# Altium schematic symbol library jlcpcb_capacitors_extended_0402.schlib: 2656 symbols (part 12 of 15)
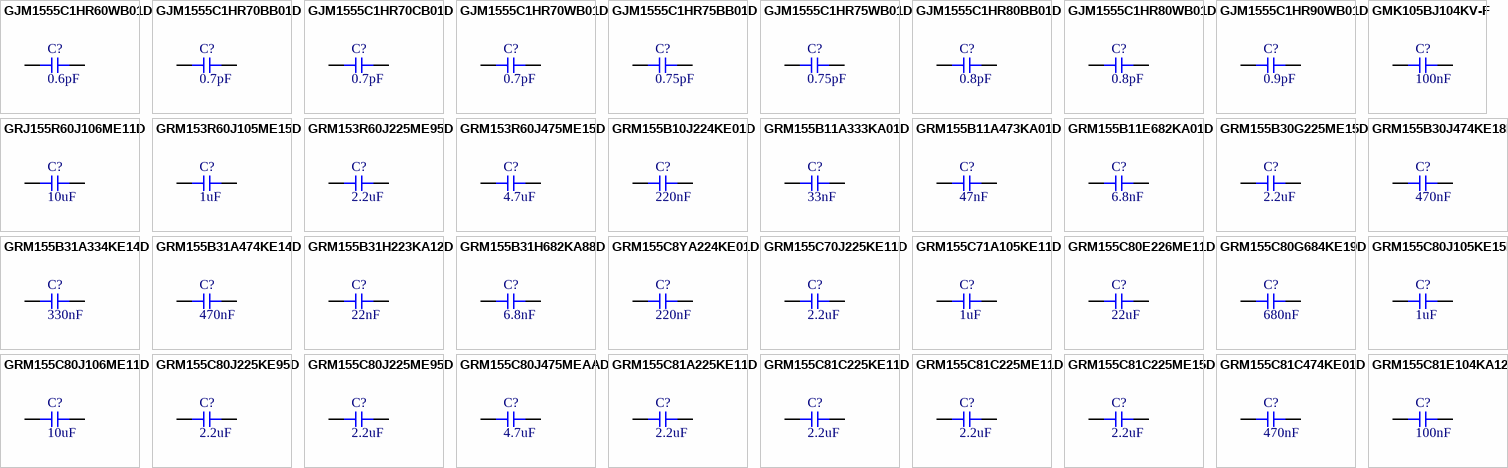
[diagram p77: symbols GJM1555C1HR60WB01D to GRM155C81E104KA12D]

## GJM1555C1HR75WB01D
designator C?  Capacitance: 0.75pF  (hidden comment: *)
Capacitor, Ceramic (MLCC), 0.75pF, ±0.05pF, 50V, C0G, ±0.05pF, SMD 0402; Manufacturer: Murata Electronics; Manufacturer Part Number: GJM1555C1HR75WB01D
footprint CAP-0402 (0402 (1005M) Capacitor)
pins: 1, 2

## GJM1555C1HR80BB01D
designator C?  Capacitance: 0.8pF  (hidden comment: *)
Capacitor, Ceramic (MLCC), 0.8pF, ±0.1pF, 50V, C0G, ±0.1pF, SMD 0402; Manufacturer: Murata Electronics; Manufacturer Part Number: GJM1555C1HR80BB01D
footprint CAP-0402 (0402 (1005M) Capacitor)
pins: 1, 2

## GJM1555C1HR80WB01D
designator C?  Capacitance: 0.8pF  (hidden comment: *)
Capacitor, Ceramic (MLCC), 0.8pF, ±0.05pF, 50V, C0G, ±0.05pF, SMD 0402; Manufacturer: Murata Electronics; Manufacturer Part Number: GJM1555C1HR80WB01D
footprint CAP-0402 (0402 (1005M) Capacitor)
pins: 1, 2

## GJM1555C1HR90WB01D
designator C?  Capacitance: 0.9pF  (hidden comment: *)
Capacitor, Ceramic (MLCC), 0.9pF, ±0.05pF, 50V, C0G, ±0.05pF, SMD 0402; Manufacturer: Murata Electronics; Manufacturer Part Number: GJM1555C1HR90WB01D
footprint CAP-0402 (0402 (1005M) Capacitor)
pins: 1, 2

## GMK105BJ104KV-F
designator C?  Capacitance: 100nF  (hidden comment: *)
Capacitor, Ceramic (MLCC), 100nF, ±10%, 35V, X5R, ±10%, SMD 0402; Manufacturer: Taiyo Yuden; Manufacturer Part Number: GMK105BJ104KV-F
footprint CAP-0402 (0402 (1005M) Capacitor)
pins: 1, 2

## GRJ155R60J106ME11D
designator C?  Capacitance: 10uF  (hidden comment: *)
Capacitor, Ceramic (MLCC), 10uF, ±20%, ±20%, SMD 0402; Manufacturer: Murata Electronics; Manufacturer Part Number: GRJ155R60J106ME11D
footprint CAP-0402 (0402 (1005M) Capacitor)
pins: 1, 2

## GRM153R60J105ME15D
designator C?  Capacitance: 1uF  (hidden comment: *)
Capacitor, Ceramic (MLCC), 1uF, ±20%, 6.3V, X5R, ±20%, SMD 0402; Manufacturer: Murata Electronics; Manufacturer Part Number: GRM153R60J105ME15D
footprint CAP-0402 (0402 (1005M) Capacitor)
pins: 1, 2

## GRM153R60J225ME95D
designator C?  Capacitance: 2.2uF  (hidden comment: *)
Capacitor, Ceramic (MLCC), 2.2uF, ±20%, 6.3V, X5R, ±20%, SMD 0402; Manufacturer: Murata Electronics; Manufacturer Part Number: GRM153R60J225ME95D
footprint CAP-0402 (0402 (1005M) Capacitor)
pins: 1, 2

## GRM153R60J475ME15D
designator C?  Capacitance: 4.7uF  (hidden comment: *)
Capacitor, Ceramic (MLCC), 4.7uF, ±20%, 6.3V, X5R, ±20%, SMD 0402; Manufacturer: Murata Electronics; Manufacturer Part Number: GRM153R60J475ME15D
footprint CAP-0402 (0402 (1005M) Capacitor)
pins: 1, 2

## GRM155B10J224KE01D
designator C?  Capacitance: 220nF  (hidden comment: *)
Capacitor, Ceramic (MLCC), 220nF, ±10%, 6.3V, B, ±10%, SMD 0402; Manufacturer: Murata Electronics; Manufacturer Part Number: GRM155B10J224KE01D
footprint CAP-0402 (0402 (1005M) Capacitor)
pins: 1, 2

## GRM155B11A333KA01D
designator C?  Capacitance: 33nF  (hidden comment: *)
Capacitor, Ceramic (MLCC), 33nF, ±10%, 10V, B, ±10%, SMD 0402; Manufacturer: Murata Electronics; Manufacturer Part Number: GRM155B11A333KA01D
footprint CAP-0402 (0402 (1005M) Capacitor)
pins: 1, 2

## GRM155B11A473KA01D
designator C?  Capacitance: 47nF  (hidden comment: *)
Capacitor, Ceramic (MLCC), 47nF, ±10%, 10V, B, ±10%, SMD 0402; Manufacturer: Murata Electronics; Manufacturer Part Number: GRM155B11A473KA01D
footprint CAP-0402 (0402 (1005M) Capacitor)
pins: 1, 2

## GRM155B11E682KA01D
designator C?  Capacitance: 6.8nF  (hidden comment: *)
Capacitor, Ceramic (MLCC), 6.8nF, ±10%, 25V, B, ±10%, SMD 0402; Manufacturer: Murata Electronics; Manufacturer Part Number: GRM155B11E682KA01D
footprint CAP-0402 (0402 (1005M) Capacitor)
pins: 1, 2

## GRM155B30G225ME15D
designator C?  Capacitance: 2.2uF  (hidden comment: *)
Capacitor, Ceramic (MLCC), 2.2uF, ±20%, 4V, B, ±20%, SMD 0402; Manufacturer: Murata Electronics; Manufacturer Part Number: GRM155B30G225ME15D
footprint CAP-0402 (0402 (1005M) Capacitor)
pins: 1, 2

## GRM155B30J474KE18D
designator C?  Capacitance: 470nF  (hidden comment: *)
Capacitor, Ceramic (MLCC), 470nF, ±10%, 6.3V, B, ±10%, SMD 0402; Manufacturer: Murata Electronics; Manufacturer Part Number: GRM155B30J474KE18D
footprint CAP-0402 (0402 (1005M) Capacitor)
pins: 1, 2

## GRM155B31A334KE14D
designator C?  Capacitance: 330nF  (hidden comment: *)
Capacitor, Ceramic (MLCC), 330nF, ±10%, 10V, B, ±10%, SMD 0402; Manufacturer: Murata Electronics; Manufacturer Part Number: GRM155B31A334KE14D
footprint CAP-0402 (0402 (1005M) Capacitor)
pins: 1, 2

## GRM155B31A474KE14D
designator C?  Capacitance: 470nF  (hidden comment: *)
Capacitor, Ceramic (MLCC), 470nF, ±10%, 10V, B, ±10%, SMD 0402; Manufacturer: Murata Electronics; Manufacturer Part Number: GRM155B31A474KE14D
footprint CAP-0402 (0402 (1005M) Capacitor)
pins: 1, 2

## GRM155B31H223KA12D
designator C?  Capacitance: 22nF  (hidden comment: *)
Capacitor, Ceramic (MLCC), 22nF, ±10%, 50V, B, ±10%, SMD 0402; Manufacturer: Murata Electronics; Manufacturer Part Number: GRM155B31H223KA12D
footprint CAP-0402 (0402 (1005M) Capacitor)
pins: 1, 2

## GRM155B31H682KA88D
designator C?  Capacitance: 6.8nF  (hidden comment: *)
Capacitor, Ceramic (MLCC), 6.8nF, ±10%, 50V, B, ±10%, SMD 0402; Manufacturer: Murata Electronics; Manufacturer Part Number: GRM155B31H682KA88D
footprint CAP-0402 (0402 (1005M) Capacitor)
pins: 1, 2

## GRM155C8YA224KE01D
designator C?  Capacitance: 220nF  (hidden comment: *)
Capacitor, Ceramic (MLCC), 220nF, ±10%, 35V, X6S, ±10%, SMD 0402; Manufacturer: Murata Electronics; Manufacturer Part Number: GRM155C8YA224KE01D
footprint CAP-0402 (0402 (1005M) Capacitor)
pins: 1, 2

## GRM155C70J225KE11D
designator C?  Capacitance: 2.2uF  (hidden comment: *)
Capacitor, Ceramic (MLCC), 2.2uF, ±10%, 6.3V, X7S, ±10%, SMD 0402; Manufacturer: Murata Electronics; Manufacturer Part Number: GRM155C70J225KE11D
footprint CAP-0402 (0402 (1005M) Capacitor)
pins: 1, 2

## GRM155C71A105KE11D
designator C?  Capacitance: 1uF  (hidden comment: *)
Capacitor, Ceramic (MLCC), 1uF, ±10%, 10V, X7S, ±10%, SMD 0402; Manufacturer: Murata Electronics; Manufacturer Part Number: GRM155C71A105KE11D
footprint CAP-0402 (0402 (1005M) Capacitor)
pins: 1, 2

## GRM155C80E226ME11D
designator C?  Capacitance: 22uF  (hidden comment: *)
Capacitor, Ceramic (MLCC), 22uF, ±20%, ±20%, SMD 0402; Manufacturer: Murata Electronics; Manufacturer Part Number: GRM155C80E226ME11D
footprint CAP-0402 (0402 (1005M) Capacitor)
pins: 1, 2

## GRM155C80G684KE19D
designator C?  Capacitance: 680nF  (hidden comment: *)
Capacitor, Ceramic (MLCC), 680nF, ±10%, 4V, X6S, ±10%, SMD 0402; Manufacturer: Murata Electronics; Manufacturer Part Number: GRM155C80G684KE19D
footprint CAP-0402 (0402 (1005M) Capacitor)
pins: 1, 2

## GRM155C80J105KE15D
designator C?  Capacitance: 1uF  (hidden comment: *)
Capacitor, Ceramic (MLCC), 1uF, ±10%, 6.3V, X6S, ±10%, SMD 0402; Manufacturer: Murata Electronics; Manufacturer Part Number: GRM155C80J105KE15D
footprint CAP-0402 (0402 (1005M) Capacitor)
pins: 1, 2

## GRM155C80J106ME11D
designator C?  Capacitance: 10uF  (hidden comment: *)
Capacitor, Ceramic (MLCC), 10uF, ±20%, 6.3V, X6S, ±20%, SMD 0402; Manufacturer: Murata Electronics; Manufacturer Part Number: GRM155C80J106ME11D
footprint CAP-0402 (0402 (1005M) Capacitor)
pins: 1, 2

## GRM155C80J225KE95D
designator C?  Capacitance: 2.2uF  (hidden comment: *)
Capacitor, Ceramic (MLCC), 2.2uF, ±10%, 6.3V, X6S, ±10%, SMD 0402; Manufacturer: Murata Electronics; Manufacturer Part Number: GRM155C80J225KE95D
footprint CAP-0402 (0402 (1005M) Capacitor)
pins: 1, 2

## GRM155C80J225ME95D
designator C?  Capacitance: 2.2uF  (hidden comment: *)
Capacitor, Ceramic (MLCC), 2.2uF, ±20%, 6.3V, X6S, ±20%, SMD 0402; Manufacturer: Murata Electronics; Manufacturer Part Number: GRM155C80J225ME95D
footprint CAP-0402 (0402 (1005M) Capacitor)
pins: 1, 2

## GRM155C80J475MEAAD
designator C?  Capacitance: 4.7uF  (hidden comment: *)
Capacitor, Ceramic (MLCC), 4.7uF, ±20%, 6.3V, X6S, ±20%, SMD 0402; Manufacturer: Murata Electronics; Manufacturer Part Number: GRM155C80J475MEAAD
footprint CAP-0402 (0402 (1005M) Capacitor)
pins: 1, 2

## GRM155C81A225KE11D
designator C?  Capacitance: 2.2uF  (hidden comment: *)
Capacitor, Ceramic (MLCC), 2.2uF, ±10%, 10V, X6S, ±10%, SMD 0402; Manufacturer: Murata Electronics; Manufacturer Part Number: GRM155C81A225KE11D
footprint CAP-0402 (0402 (1005M) Capacitor)
pins: 1, 2

## GRM155C81C225KE11D
designator C?  Capacitance: 2.2uF  (hidden comment: *)
Capacitor, Ceramic (MLCC), 2.2uF, ±10%, ±10%, SMD 0402; Manufacturer: Murata Electronics; Manufacturer Part Number: GRM155C81C225KE11D
footprint CAP-0402 (0402 (1005M) Capacitor)
pins: 1, 2

## GRM155C81C225ME11D
designator C?  Capacitance: 2.2uF  (hidden comment: *)
Capacitor, Ceramic (MLCC), 2.2uF, ±20%, 16V, X6S, ±20%, SMD 0402; Manufacturer: Murata Electronics; Manufacturer Part Number: GRM155C81C225ME11D
footprint CAP-0402 (0402 (1005M) Capacitor)
pins: 1, 2

## GRM155C81C225ME15D
designator C?  Capacitance: 2.2uF  (hidden comment: *)
Capacitor, Ceramic (MLCC), 2.2uF, ±20%, ±20%, SMD 0402; Manufacturer: Murata Electronics; Manufacturer Part Number: GRM155C81C225ME15D
footprint CAP-0402 (0402 (1005M) Capacitor)
pins: 1, 2

## GRM155C81C474KE01D
designator C?  Capacitance: 470nF  (hidden comment: *)
Capacitor, Ceramic (MLCC), 470nF, ±10%, 16V, X6S, ±10%, SMD 0402; Manufacturer: Murata Electronics; Manufacturer Part Number: GRM155C81C474KE01D
footprint CAP-0402 (0402 (1005M) Capacitor)
pins: 1, 2

## GRM155C81E104KA12D
designator C?  Capacitance: 100nF  (hidden comment: *)
Capacitor, Ceramic (MLCC), 100nF, ±10%, 25V, X6S, ±10%, SMD 0402; Manufacturer: Murata Electronics; Manufacturer Part Number: GRM155C81E104KA12D
footprint CAP-0402 (0402 (1005M) Capacitor)
pins: 1, 2

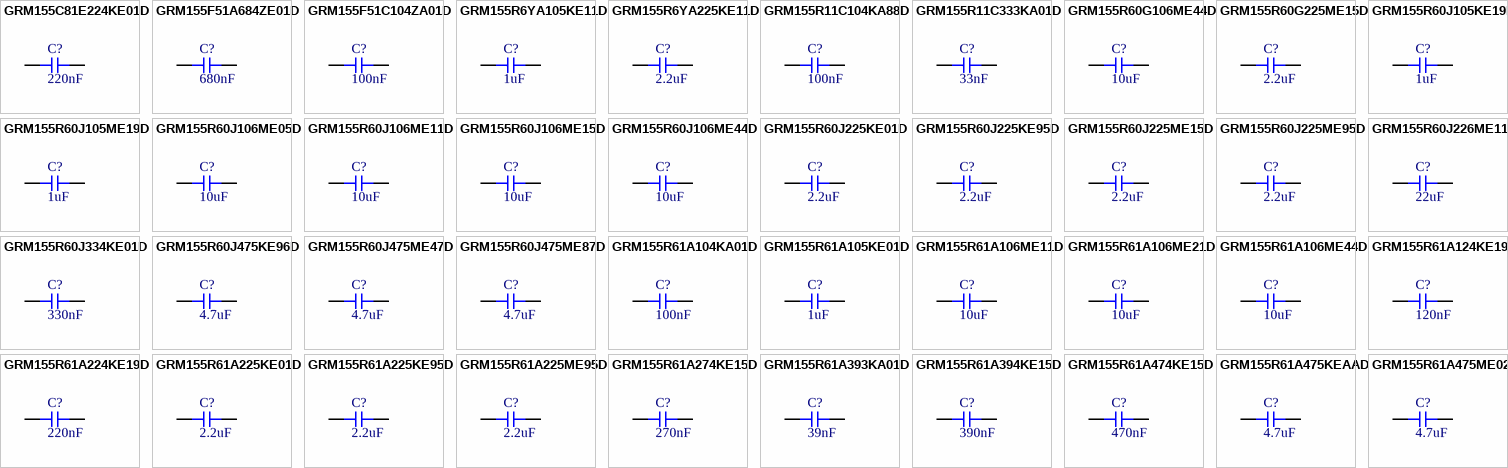
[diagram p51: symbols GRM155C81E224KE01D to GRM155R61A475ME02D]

## GRM155C81E224KE01D
designator C?  Capacitance: 220nF  (hidden comment: *)
Capacitor, Ceramic (MLCC), 220nF, ±10%, 25V, X6S, ±10%, SMD 0402; Manufacturer: Murata Electronics; Manufacturer Part Number: GRM155C81E224KE01D
footprint CAP-0402 (0402 (1005M) Capacitor)
pins: 1, 2

## GRM155F51A684ZE01D
designator C?  Capacitance: 680nF  (hidden comment: *)
Capacitor, Ceramic (MLCC), 680nF, 10V, SMD 0402; Manufacturer: Murata Electronics; Manufacturer Part Number: GRM155F51A684ZE01D; Temperature Rating: -20%~+80%
footprint CAP-0402 (0402 (1005M) Capacitor)
pins: 1, 2

## GRM155F51C104ZA01D
designator C?  Capacitance: 100nF  (hidden comment: *)
Capacitor, Ceramic (MLCC), 100nF, 16V, Y5V, SMD 0402; Manufacturer: Murata Electronics; Manufacturer Part Number: GRM155F51C104ZA01D; Temperature Rating: -20%~+80%
footprint CAP-0402 (0402 (1005M) Capacitor)
pins: 1, 2

## GRM155R6YA105KE11D
designator C?  Capacitance: 1uF  (hidden comment: *)
Capacitor, Ceramic (MLCC), 1uF, ±10%, ±10%, SMD 0402; Manufacturer: Murata Electronics; Manufacturer Part Number: GRM155R6YA105KE11D
footprint CAP-0402 (0402 (1005M) Capacitor)
pins: 1, 2

## GRM155R6YA225KE11D
designator C?  Capacitance: 2.2uF  (hidden comment: *)
Capacitor, Ceramic (MLCC), 2.2uF, ±10%, 35V, X5R, ±10%, SMD 0402; Manufacturer: Murata Electronics; Manufacturer Part Number: GRM155R6YA225KE11D
footprint CAP-0402 (0402 (1005M) Capacitor)
pins: 1, 2

## GRM155R11C104KA88D
designator C?  Capacitance: 100nF  (hidden comment: *)
Capacitor, Ceramic (MLCC), 100nF, ±10%, 16V, R, ±10%, SMD 0402; Manufacturer: Murata Electronics; Manufacturer Part Number: GRM155R11C104KA88D
footprint CAP-0402 (0402 (1005M) Capacitor)
pins: 1, 2

## GRM155R11C333KA01D
designator C?  Capacitance: 33nF  (hidden comment: *)
Capacitor, Ceramic (MLCC), 33nF, ±10%, 16V, R, ±10%, SMD 0402; Manufacturer: Murata Electronics; Manufacturer Part Number: GRM155R11C333KA01D
footprint CAP-0402 (0402 (1005M) Capacitor)
pins: 1, 2

## GRM155R60G106ME44D
designator C?  Capacitance: 10uF  (hidden comment: *)
Capacitor, Ceramic (MLCC), 10uF, ±20%, 4V, X5R, ±20%, SMD 0402; Manufacturer: Murata Electronics; Manufacturer Part Number: GRM155R60G106ME44D
footprint CAP-0402 (0402 (1005M) Capacitor)
pins: 1, 2

## GRM155R60G225ME15D
designator C?  Capacitance: 2.2uF  (hidden comment: *)
Capacitor, Ceramic (MLCC), 2.2uF, ±20%, 4V, X5R, ±20%, SMD 0402; Manufacturer: Murata Electronics; Manufacturer Part Number: GRM155R60G225ME15D
footprint CAP-0402 (0402 (1005M) Capacitor)
pins: 1, 2

## GRM155R60J105KE19D
designator C?  Capacitance: 1uF  (hidden comment: *)
Capacitor, Ceramic (MLCC), 1uF, ±10%, 6.3V, X5R, ±10%, SMD 0402; Manufacturer: Murata Electronics; Manufacturer Part Number: GRM155R60J105KE19D
footprint CAP-0402 (0402 (1005M) Capacitor)
pins: 1, 2

## GRM155R60J105ME19D
designator C?  Capacitance: 1uF  (hidden comment: *)
Capacitor, Ceramic (MLCC), 1uF, ±20%, 6.3V, X5R, ±20%, SMD 0402; Manufacturer: Murata Electronics; Manufacturer Part Number: GRM155R60J105ME19D
footprint CAP-0402 (0402 (1005M) Capacitor)
pins: 1, 2

## GRM155R60J106ME05D
designator C?  Capacitance: 10uF  (hidden comment: *)
Capacitor, Ceramic (MLCC), 10uF, ±20%, 6.3V, X5R, ±20%, SMD 0402; Manufacturer: Murata Electronics; Manufacturer Part Number: GRM155R60J106ME05D
footprint CAP-0402 (0402 (1005M) Capacitor)
pins: 1, 2

## GRM155R60J106ME11D
designator C?  Capacitance: 10uF  (hidden comment: *)
Capacitor, Ceramic (MLCC), 10uF, ±20%, 6.3V, ±20%, SMD 0402; Manufacturer: Murata Electronics; Manufacturer Part Number: GRM155R60J106ME11D
footprint CAP-0402 (0402 (1005M) Capacitor)
pins: 1, 2

## GRM155R60J106ME15D
designator C?  Capacitance: 10uF  (hidden comment: *)
Capacitor, Ceramic (MLCC), 10uF, ±20%, 6.3V, X5R, ±20%, SMD 0402; Manufacturer: Murata Electronics; Manufacturer Part Number: GRM155R60J106ME15D
footprint CAP-0402 (0402 (1005M) Capacitor)
pins: 1, 2

## GRM155R60J106ME44D
designator C?  Capacitance: 10uF  (hidden comment: *)
Capacitor, Ceramic (MLCC), 10uF, ±20%, 6.3V, X5R, ±20%, SMD 0402; Manufacturer: Murata Electronics; Manufacturer Part Number: GRM155R60J106ME44D
footprint CAP-0402 (0402 (1005M) Capacitor)
pins: 1, 2

## GRM155R60J225KE01D
designator C?  Capacitance: 2.2uF  (hidden comment: *)
Capacitor, Ceramic (MLCC), 2.2uF, ±10%, 6.3V, X5R, ±10%, SMD 0402; Manufacturer: Murata Electronics; Manufacturer Part Number: GRM155R60J225KE01D
footprint CAP-0402 (0402 (1005M) Capacitor)
pins: 1, 2

## GRM155R60J225KE95D
designator C?  Capacitance: 2.2uF  (hidden comment: *)
Capacitor, Ceramic (MLCC), 2.2uF, ±10%, 6.3V, X5R, ±10%, SMD 0402; Manufacturer: Murata Electronics; Manufacturer Part Number: GRM155R60J225KE95D
footprint CAP-0402 (0402 (1005M) Capacitor)
pins: 1, 2

## GRM155R60J225ME15D
designator C?  Capacitance: 2.2uF  (hidden comment: *)
Capacitor, Ceramic (MLCC), 2.2uF, ±20%, 6.3V, X5R, ±20%, SMD 0402; Manufacturer: Murata Electronics; Manufacturer Part Number: GRM155R60J225ME15D
footprint CAP-0402 (0402 (1005M) Capacitor)
pins: 1, 2

## GRM155R60J225ME95D
designator C?  Capacitance: 2.2uF  (hidden comment: *)
Capacitor, Ceramic (MLCC), 2.2uF, ±20%, 6.3V, X5R, ±20%, SMD 0402; Manufacturer: Murata Electronics; Manufacturer Part Number: GRM155R60J225ME95D
footprint CAP-0402 (0402 (1005M) Capacitor)
pins: 1, 2

## GRM155R60J226ME11D
designator C?  Capacitance: 22uF  (hidden comment: *)
Capacitor, Ceramic (MLCC), 22uF, ±20%, 6.3V, X5R, ±20%, SMD 0402; Manufacturer: Murata Electronics; Manufacturer Part Number: GRM155R60J226ME11D
footprint CAP-0402 (0402 (1005M) Capacitor)
pins: 1, 2

## GRM155R60J334KE01D
designator C?  Capacitance: 330nF  (hidden comment: *)
Capacitor, Ceramic (MLCC), 330nF, ±10%, 6.3V, X5R, ±10%, SMD 0402; Manufacturer: Murata Electronics; Manufacturer Part Number: GRM155R60J334KE01D
footprint CAP-0402 (0402 (1005M) Capacitor)
pins: 1, 2

## GRM155R60J475KE96D
designator C?  Capacitance: 4.7uF  (hidden comment: *)
Capacitor, Ceramic (MLCC), 4.7uF, ±10%, 6.3V, X5R, ±10%, SMD 0402; Manufacturer: Murata Electronics; Manufacturer Part Number: GRM155R60J475KE96D
footprint CAP-0402 (0402 (1005M) Capacitor)
pins: 1, 2

## GRM155R60J475ME47D
designator C?  Capacitance: 4.7uF  (hidden comment: *)
Capacitor, Ceramic (MLCC), 4.7uF, ±20%, 6.3V, X5R, ±20%, SMD 0402; Manufacturer: Murata Electronics; Manufacturer Part Number: GRM155R60J475ME47D
footprint CAP-0402 (0402 (1005M) Capacitor)
pins: 1, 2

## GRM155R60J475ME87D
designator C?  Capacitance: 4.7uF  (hidden comment: *)
Capacitor, Ceramic (MLCC), 4.7uF, ±20%, 6.3V, X5R, ±20%, SMD 0402; Manufacturer: Murata Electronics; Manufacturer Part Number: GRM155R60J475ME87D
footprint CAP-0402 (0402 (1005M) Capacitor)
pins: 1, 2

## GRM155R61A104KA01D
designator C?  Capacitance: 100nF  (hidden comment: *)
Capacitor, Ceramic (MLCC), 100nF, ±10%, 10V, X5R, ±10%, SMD 0402; Manufacturer: Murata Electronics; Manufacturer Part Number: GRM155R61A104KA01D
footprint CAP-0402 (0402 (1005M) Capacitor)
pins: 1, 2

## GRM155R61A105KE01D
designator C?  Capacitance: 1uF  (hidden comment: *)
Capacitor, Ceramic (MLCC), 1uF, ±10%, 10V, X5R, ±10%, SMD 0402; Manufacturer: Murata Electronics; Manufacturer Part Number: GRM155R61A105KE01D
footprint CAP-0402 (0402 (1005M) Capacitor)
pins: 1, 2

## GRM155R61A106ME11D
designator C?  Capacitance: 10uF  (hidden comment: *)
Capacitor, Ceramic (MLCC), 10uF, ±20%, 10V, X5R, ±20%, SMD 0402; Manufacturer: Murata Electronics; Manufacturer Part Number: GRM155R61A106ME11D
footprint CAP-0402 (0402 (1005M) Capacitor)
pins: 1, 2

## GRM155R61A106ME21D
designator C?  Capacitance: 10uF  (hidden comment: *)
Capacitor, Ceramic (MLCC), 10uF, ±20%, 10V, X5R, ±20%, SMD 0402; Manufacturer: Murata Electronics; Manufacturer Part Number: GRM155R61A106ME21D
footprint CAP-0402 (0402 (1005M) Capacitor)
pins: 1, 2

## GRM155R61A106ME44D
designator C?  Capacitance: 10uF  (hidden comment: *)
Capacitor, Ceramic (MLCC), 10uF, ±20%, 10V, X5R, ±20%, SMD 0402; Manufacturer: Murata Electronics; Manufacturer Part Number: GRM155R61A106ME44D
footprint CAP-0402 (0402 (1005M) Capacitor)
pins: 1, 2

## GRM155R61A124KE19D
designator C?  Capacitance: 120nF  (hidden comment: *)
Capacitor, Ceramic (MLCC), 120nF, ±10%, ±10%, SMD 0402; Manufacturer: Murata Electronics; Manufacturer Part Number: GRM155R61A124KE19D
footprint CAP-0402 (0402 (1005M) Capacitor)
pins: 1, 2

## GRM155R61A224KE19D
designator C?  Capacitance: 220nF  (hidden comment: *)
Capacitor, Ceramic (MLCC), 220nF, ±10%, 10V, X5R, ±10%, SMD 0402; Manufacturer: Murata Electronics; Manufacturer Part Number: GRM155R61A224KE19D
footprint CAP-0402 (0402 (1005M) Capacitor)
pins: 1, 2

## GRM155R61A225KE01D
designator C?  Capacitance: 2.2uF  (hidden comment: *)
Capacitor, Ceramic (MLCC), 2.2uF, ±10%, ±10%, SMD 0402; Manufacturer: Murata Electronics; Manufacturer Part Number: GRM155R61A225KE01D
footprint CAP-0402 (0402 (1005M) Capacitor)
pins: 1, 2

## GRM155R61A225KE95D
designator C?  Capacitance: 2.2uF  (hidden comment: *)
Capacitor, Ceramic (MLCC), 2.2uF, ±10%, 10V, X5R, ±10%, SMD 0402; Manufacturer: Murata Electronics; Manufacturer Part Number: GRM155R61A225KE95D
footprint CAP-0402 (0402 (1005M) Capacitor)
pins: 1, 2

## GRM155R61A225ME95D
designator C?  Capacitance: 2.2uF  (hidden comment: *)
Capacitor, Ceramic (MLCC), 2.2uF, ±20%, 10V, X5R, ±20%, SMD 0402; Manufacturer: Murata Electronics; Manufacturer Part Number: GRM155R61A225ME95D
footprint CAP-0402 (0402 (1005M) Capacitor)
pins: 1, 2

## GRM155R61A274KE15D
designator C?  Capacitance: 270nF  (hidden comment: *)
Capacitor, Ceramic (MLCC), 270nF, ±10%, ±10%, SMD 0402; Manufacturer: Murata Electronics; Manufacturer Part Number: GRM155R61A274KE15D
footprint CAP-0402 (0402 (1005M) Capacitor)
pins: 1, 2

## GRM155R61A393KA01D
designator C?  Capacitance: 39nF  (hidden comment: *)
Capacitor, Ceramic (MLCC), 39nF, ±10%, 10V, X5R, ±10%, SMD 0402; Manufacturer: Murata Electronics; Manufacturer Part Number: GRM155R61A393KA01D
footprint CAP-0402 (0402 (1005M) Capacitor)
pins: 1, 2

## GRM155R61A394KE15D
designator C?  Capacitance: 390nF  (hidden comment: *)
Capacitor, Ceramic (MLCC), 390nF, ±10%, 10V, X5R, ±10%, SMD 0402; Manufacturer: Murata Electronics; Manufacturer Part Number: GRM155R61A394KE15D
footprint CAP-0402 (0402 (1005M) Capacitor)
pins: 1, 2

## GRM155R61A474KE15D
designator C?  Capacitance: 470nF  (hidden comment: *)
Capacitor, Ceramic (MLCC), 470nF, ±10%, 10V, X5R, ±10%, SMD 0402; Manufacturer: Murata Electronics; Manufacturer Part Number: GRM155R61A474KE15D
footprint CAP-0402 (0402 (1005M) Capacitor)
pins: 1, 2

## GRM155R61A475KEAAD
designator C?  Capacitance: 4.7uF  (hidden comment: *)
Capacitor, Ceramic (MLCC), 4.7uF, ±10%, 10V, X5R, ±10%, SMD 0402; Manufacturer: Murata Electronics; Manufacturer Part Number: GRM155R61A475KEAAD
footprint CAP-0402 (0402 (1005M) Capacitor)
pins: 1, 2

## GRM155R61A475ME02D
designator C?  Capacitance: 4.7uF  (hidden comment: *)
Capacitor, Ceramic (MLCC), 4.7uF, ±20%, 10V, X5R, ±20%, SMD 0402; Manufacturer: Murata Electronics; Manufacturer Part Number: GRM155R61A475ME02D
footprint CAP-0402 (0402 (1005M) Capacitor)
pins: 1, 2

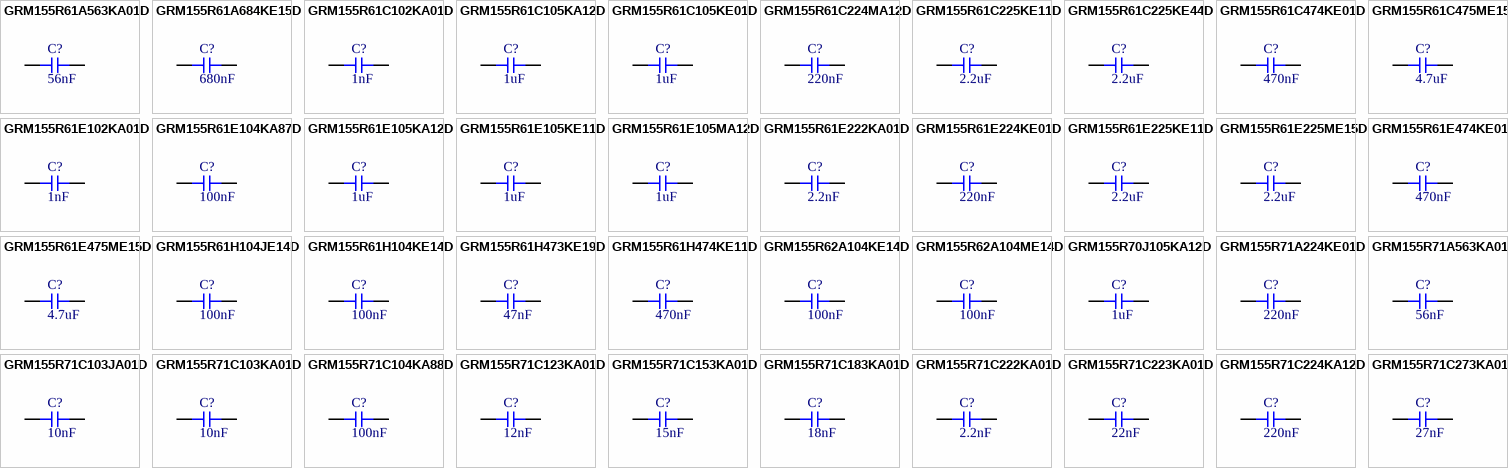
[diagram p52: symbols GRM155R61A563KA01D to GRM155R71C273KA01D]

## GRM155R61A563KA01D
designator C?  Capacitance: 56nF  (hidden comment: *)
Capacitor, Ceramic (MLCC), 56nF, ±10%, 10V, X5R, ±10%, SMD 0402; Manufacturer: Murata Electronics; Manufacturer Part Number: GRM155R61A563KA01D
footprint CAP-0402 (0402 (1005M) Capacitor)
pins: 1, 2

## GRM155R61A684KE15D
designator C?  Capacitance: 680nF  (hidden comment: *)
Capacitor, Ceramic (MLCC), 680nF, ±10%, 10V, X5R, ±10%, SMD 0402; Manufacturer: Murata Electronics; Manufacturer Part Number: GRM155R61A684KE15D
footprint CAP-0402 (0402 (1005M) Capacitor)
pins: 1, 2

## GRM155R61C102KA01D
designator C?  Capacitance: 1nF  (hidden comment: *)
Capacitor, Ceramic (MLCC), 1nF, ±10%, 16V, X5R, ±10%, SMD 0402; Manufacturer: Murata Electronics; Manufacturer Part Number: GRM155R61C102KA01D
footprint CAP-0402 (0402 (1005M) Capacitor)
pins: 1, 2

## GRM155R61C105KA12D
designator C?  Capacitance: 1uF  (hidden comment: *)
Capacitor, Ceramic (MLCC), 1uF, ±10%, 16V, X5R, ±10%, SMD 0402; Manufacturer: Murata Electronics; Manufacturer Part Number: GRM155R61C105KA12D
footprint CAP-0402 (0402 (1005M) Capacitor)
pins: 1, 2

## GRM155R61C105KE01D
designator C?  Capacitance: 1uF  (hidden comment: *)
Capacitor, Ceramic (MLCC), 1uF, ±10%, 16V, X5R, ±10%, SMD 0402; Manufacturer: Murata Electronics; Manufacturer Part Number: GRM155R61C105KE01D
footprint CAP-0402 (0402 (1005M) Capacitor)
pins: 1, 2

## GRM155R61C224MA12D
designator C?  Capacitance: 220nF  (hidden comment: *)
Capacitor, Ceramic (MLCC), 220nF, ±20%, 16V, X5R, ±20%, SMD 0402; Manufacturer: Murata Electronics; Manufacturer Part Number: GRM155R61C224MA12D
footprint CAP-0402 (0402 (1005M) Capacitor)
pins: 1, 2

## GRM155R61C225KE11D
designator C?  Capacitance: 2.2uF  (hidden comment: *)
Capacitor, Ceramic (MLCC), 2.2uF, ±10%, 16V, X5R, ±10%, SMD 0402; Manufacturer: Murata Electronics; Manufacturer Part Number: GRM155R61C225KE11D
footprint CAP-0402 (0402 (1005M) Capacitor)
pins: 1, 2

## GRM155R61C225KE44D
designator C?  Capacitance: 2.2uF  (hidden comment: *)
Capacitor, Ceramic (MLCC), 2.2uF, ±10%, 16V, X5R, ±10%, SMD 0402; Manufacturer: Murata Electronics; Manufacturer Part Number: GRM155R61C225KE44D
footprint CAP-0402 (0402 (1005M) Capacitor)
pins: 1, 2

## GRM155R61C474KE01D
designator C?  Capacitance: 470nF  (hidden comment: *)
Capacitor, Ceramic (MLCC), 470nF, ±10%, 16V, X5R, ±10%, SMD 0402; Manufacturer: Murata Electronics; Manufacturer Part Number: GRM155R61C474KE01D
footprint CAP-0402 (0402 (1005M) Capacitor)
pins: 1, 2

## GRM155R61C475ME15D
designator C?  Capacitance: 4.7uF  (hidden comment: *)
Capacitor, Ceramic (MLCC), 4.7uF, ±20%, ±20%, SMD 0402; Manufacturer: Murata Electronics; Manufacturer Part Number: GRM155R61C475ME15D
footprint CAP-0402 (0402 (1005M) Capacitor)
pins: 1, 2

## GRM155R61E102KA01D
designator C?  Capacitance: 1nF  (hidden comment: *)
Capacitor, Ceramic (MLCC), 1nF, ±10%, 25V, X5R, ±10%, SMD 0402; Manufacturer: Murata Electronics; Manufacturer Part Number: GRM155R61E102KA01D
footprint CAP-0402 (0402 (1005M) Capacitor)
pins: 1, 2

## GRM155R61E104KA87D
designator C?  Capacitance: 100nF  (hidden comment: *)
Capacitor, Ceramic (MLCC), 100nF, ±10%, 25V, X5R, ±10%, SMD 0402; Manufacturer: Murata Electronics; Manufacturer Part Number: GRM155R61E104KA87D
footprint CAP-0402 (0402 (1005M) Capacitor)
pins: 1, 2

## GRM155R61E105KA12D
designator C?  Capacitance: 1uF  (hidden comment: *)
Capacitor, Ceramic (MLCC), 1uF, ±10%, 25V, X5R, ±10%, SMD 0402; Manufacturer: Murata Electronics; Manufacturer Part Number: GRM155R61E105KA12D
footprint CAP-0402 (0402 (1005M) Capacitor)
pins: 1, 2

## GRM155R61E105KE11D
designator C?  Capacitance: 1uF  (hidden comment: *)
Capacitor, Ceramic (MLCC), 1uF, ±10%, 25V, X5R, ±10%, SMD 0402; Manufacturer: Murata Electronics; Manufacturer Part Number: GRM155R61E105KE11D
footprint CAP-0402 (0402 (1005M) Capacitor)
pins: 1, 2

## GRM155R61E105MA12D
designator C?  Capacitance: 1uF  (hidden comment: *)
Capacitor, Ceramic (MLCC), 1uF, ±20%, 25V, X5R, ±20%, SMD 0402; Manufacturer: Murata Electronics; Manufacturer Part Number: GRM155R61E105MA12D
footprint CAP-0402 (0402 (1005M) Capacitor)
pins: 1, 2

## GRM155R61E222KA01D
designator C?  Capacitance: 2.2nF  (hidden comment: *)
Capacitor, Ceramic (MLCC), 2.2nF, ±10%, 25V, X5R, ±10%, SMD 0402; Manufacturer: Murata Electronics; Manufacturer Part Number: GRM155R61E222KA01D
footprint CAP-0402 (0402 (1005M) Capacitor)
pins: 1, 2

## GRM155R61E224KE01D
designator C?  Capacitance: 220nF  (hidden comment: *)
Capacitor, Ceramic (MLCC), 220nF, ±10%, 25V, X5R, ±10%, SMD 0402; Manufacturer: Murata Electronics; Manufacturer Part Number: GRM155R61E224KE01D
footprint CAP-0402 (0402 (1005M) Capacitor)
pins: 1, 2

## GRM155R61E225KE11D
designator C?  Capacitance: 2.2uF  (hidden comment: *)
Capacitor, Ceramic (MLCC), 2.2uF, ±10%, 25V, X5R, ±10%, SMD 0402; Manufacturer: Murata Electronics; Manufacturer Part Number: GRM155R61E225KE11D
footprint CAP-0402 (0402 (1005M) Capacitor)
pins: 1, 2

## GRM155R61E225ME15D
designator C?  Capacitance: 2.2uF  (hidden comment: *)
Capacitor, Ceramic (MLCC), 2.2uF, ±20%, 25V, X5R, ±20%, SMD 0402; Manufacturer: Murata Electronics; Manufacturer Part Number: GRM155R61E225ME15D
footprint CAP-0402 (0402 (1005M) Capacitor)
pins: 1, 2

## GRM155R61E474KE01D
designator C?  Capacitance: 470nF  (hidden comment: *)
Capacitor, Ceramic (MLCC), 470nF, ±10%, 25V, X5R, ±10%, SMD 0402; Manufacturer: Murata Electronics; Manufacturer Part Number: GRM155R61E474KE01D
footprint CAP-0402 (0402 (1005M) Capacitor)
pins: 1, 2

## GRM155R61E475ME15D
designator C?  Capacitance: 4.7uF  (hidden comment: *)
Capacitor, Ceramic (MLCC), 4.7uF, ±20%, 25V, X5R, ±20%, SMD 0402; Manufacturer: Murata Electronics; Manufacturer Part Number: GRM155R61E475ME15D
footprint CAP-0402 (0402 (1005M) Capacitor)
pins: 1, 2

## GRM155R61H104JE14D
designator C?  Capacitance: 100nF  (hidden comment: *)
Capacitor, Ceramic (MLCC), 100nF, ±5%, ±5%, SMD 0402; Manufacturer: Murata Electronics; Manufacturer Part Number: GRM155R61H104JE14D
footprint CAP-0402 (0402 (1005M) Capacitor)
pins: 1, 2

## GRM155R61H104KE14D
designator C?  Capacitance: 100nF  (hidden comment: *)
Capacitor, Ceramic (MLCC), 100nF, ±10%, 50V, X5R, ±10%, SMD 0402; Manufacturer: Murata Electronics; Manufacturer Part Number: GRM155R61H104KE14D
footprint CAP-0402 (0402 (1005M) Capacitor)
pins: 1, 2

## GRM155R61H473KE19D
designator C?  Capacitance: 47nF  (hidden comment: *)
Capacitor, Ceramic (MLCC), 47nF, ±10%, ±10%, SMD 0402; Manufacturer: Murata Electronics; Manufacturer Part Number: GRM155R61H473KE19D
footprint CAP-0402 (0402 (1005M) Capacitor)
pins: 1, 2

## GRM155R61H474KE11D
designator C?  Capacitance: 470nF  (hidden comment: *)
Capacitor, Ceramic (MLCC), 470nF, ±10%, 50V, X5R, ±10%, SMD 0402; Manufacturer: Murata Electronics; Manufacturer Part Number: GRM155R61H474KE11D
footprint CAP-0402 (0402 (1005M) Capacitor)
pins: 1, 2

## GRM155R62A104KE14D
designator C?  Capacitance: 100nF  (hidden comment: *)
Capacitor, Ceramic (MLCC), 100nF, ±10%, 100V, ±10%, SMD 0402; Manufacturer: Murata Electronics; Manufacturer Part Number: GRM155R62A104KE14D
footprint CAP-0402 (0402 (1005M) Capacitor)
pins: 1, 2

## GRM155R62A104ME14D
designator C?  Capacitance: 100nF  (hidden comment: *)
Capacitor, Ceramic (MLCC), 100nF, ±20%, 100V, X5R, ±20%, SMD 0402; Manufacturer: Murata Electronics; Manufacturer Part Number: GRM155R62A104ME14D
footprint CAP-0402 (0402 (1005M) Capacitor)
pins: 1, 2

## GRM155R70J105KA12D
designator C?  Capacitance: 1uF  (hidden comment: *)
Capacitor, Ceramic (MLCC), 1uF, ±10%, 6.3V, X7R, ±10%, SMD 0402; Manufacturer: Murata Electronics; Manufacturer Part Number: GRM155R70J105KA12D
footprint CAP-0402 (0402 (1005M) Capacitor)
pins: 1, 2

## GRM155R71A224KE01D
designator C?  Capacitance: 220nF  (hidden comment: *)
Capacitor, Ceramic (MLCC), 220nF, ±10%, 10V, X7R, ±10%, SMD 0402; Manufacturer: Murata Electronics; Manufacturer Part Number: GRM155R71A224KE01D
footprint CAP-0402 (0402 (1005M) Capacitor)
pins: 1, 2

## GRM155R71A563KA01D
designator C?  Capacitance: 56nF  (hidden comment: *)
Capacitor, Ceramic (MLCC), 56nF, ±10%, 10V, X7R, ±10%, SMD 0402; Manufacturer: Murata Electronics; Manufacturer Part Number: GRM155R71A563KA01D
footprint CAP-0402 (0402 (1005M) Capacitor)
pins: 1, 2

## GRM155R71C103JA01D
designator C?  Capacitance: 10nF  (hidden comment: *)
Capacitor, Ceramic (MLCC), 10nF, ±5%, 16V, X7R, ±5%, SMD 0402; Manufacturer: Murata Electronics; Manufacturer Part Number: GRM155R71C103JA01D
footprint CAP-0402 (0402 (1005M) Capacitor)
pins: 1, 2

## GRM155R71C103KA01D
designator C?  Capacitance: 10nF  (hidden comment: *)
Capacitor, Ceramic (MLCC), 10nF, ±10%, 16V, X7R, ±10%, SMD 0402; Manufacturer: Murata Electronics; Manufacturer Part Number: GRM155R71C103KA01D
footprint CAP-0402 (0402 (1005M) Capacitor)
pins: 1, 2

## GRM155R71C104KA88D
designator C?  Capacitance: 100nF  (hidden comment: *)
Capacitor, Ceramic (MLCC), 100nF, ±10%, 16V, X7R, ±10%, SMD 0402; Manufacturer: Murata Electronics; Manufacturer Part Number: GRM155R71C104KA88D
footprint CAP-0402 (0402 (1005M) Capacitor)
pins: 1, 2

## GRM155R71C123KA01D
designator C?  Capacitance: 12nF  (hidden comment: *)
Capacitor, Ceramic (MLCC), 12nF, ±10%, ±10%, SMD 0402; Manufacturer: Murata Electronics; Manufacturer Part Number: GRM155R71C123KA01D
footprint CAP-0402 (0402 (1005M) Capacitor)
pins: 1, 2

## GRM155R71C153KA01D
designator C?  Capacitance: 15nF  (hidden comment: *)
Capacitor, Ceramic (MLCC), 15nF, ±10%, 16V, X7R, ±10%, SMD 0402; Manufacturer: Murata Electronics; Manufacturer Part Number: GRM155R71C153KA01D
footprint CAP-0402 (0402 (1005M) Capacitor)
pins: 1, 2

## GRM155R71C183KA01D
designator C?  Capacitance: 18nF  (hidden comment: *)
Capacitor, Ceramic (MLCC), 18nF, ±10%, 16V, X7R, ±10%, SMD 0402; Manufacturer: Murata Electronics; Manufacturer Part Number: GRM155R71C183KA01D
footprint CAP-0402 (0402 (1005M) Capacitor)
pins: 1, 2

## GRM155R71C222KA01D
designator C?  Capacitance: 2.2nF  (hidden comment: *)
Capacitor, Ceramic (MLCC), 2.2nF, ±10%, ±10%, SMD 0402; Manufacturer: Murata Electronics; Manufacturer Part Number: GRM155R71C222KA01D
footprint CAP-0402 (0402 (1005M) Capacitor)
pins: 1, 2

## GRM155R71C223KA01D
designator C?  Capacitance: 22nF  (hidden comment: *)
Capacitor, Ceramic (MLCC), 22nF, ±10%, 16V, X7R, ±10%, SMD 0402; Manufacturer: Murata Electronics; Manufacturer Part Number: GRM155R71C223KA01D
footprint CAP-0402 (0402 (1005M) Capacitor)
pins: 1, 2

## GRM155R71C224KA12D
designator C?  Capacitance: 220nF  (hidden comment: *)
Capacitor, Ceramic (MLCC), 220nF, ±10%, 16V, X7R, ±10%, SMD 0402; Manufacturer: Murata Electronics; Manufacturer Part Number: GRM155R71C224KA12D
footprint CAP-0402 (0402 (1005M) Capacitor)
pins: 1, 2

## GRM155R71C273KA01D
designator C?  Capacitance: 27nF  (hidden comment: *)
Capacitor, Ceramic (MLCC), 27nF, ±10%, 16V, X7R, ±10%, SMD 0402; Manufacturer: Murata Electronics; Manufacturer Part Number: GRM155R71C273KA01D
footprint CAP-0402 (0402 (1005M) Capacitor)
pins: 1, 2

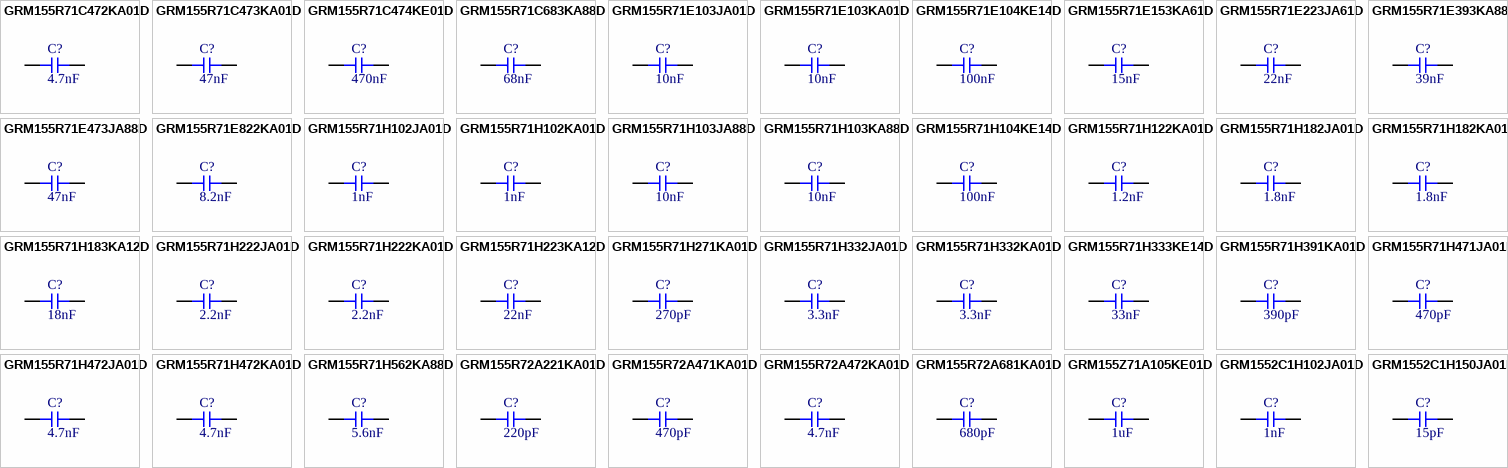
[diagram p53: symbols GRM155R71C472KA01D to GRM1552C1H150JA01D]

## GRM155R71C472KA01D
designator C?  Capacitance: 4.7nF  (hidden comment: *)
Capacitor, Ceramic (MLCC), 4.7nF, ±10%, 16V, X7R, ±10%, SMD 0402; Manufacturer: Murata Electronics; Manufacturer Part Number: GRM155R71C472KA01D
footprint CAP-0402 (0402 (1005M) Capacitor)
pins: 1, 2

## GRM155R71C473KA01D
designator C?  Capacitance: 47nF  (hidden comment: *)
Capacitor, Ceramic (MLCC), 47nF, ±10%, 16V, X7R, ±10%, SMD 0402; Manufacturer: Murata Electronics; Manufacturer Part Number: GRM155R71C473KA01D
footprint CAP-0402 (0402 (1005M) Capacitor)
pins: 1, 2

## GRM155R71C474KE01D
designator C?  Capacitance: 470nF  (hidden comment: *)
Capacitor, Ceramic (MLCC), 470nF, ±10%, 16V, X7R, ±10%, SMD 0402; Manufacturer: Murata Electronics; Manufacturer Part Number: GRM155R71C474KE01D
footprint CAP-0402 (0402 (1005M) Capacitor)
pins: 1, 2

## GRM155R71C683KA88D
designator C?  Capacitance: 68nF  (hidden comment: *)
Capacitor, Ceramic (MLCC), 68nF, ±10%, 16V, X7R, ±10%, SMD 0402; Manufacturer: Murata Electronics; Manufacturer Part Number: GRM155R71C683KA88D
footprint CAP-0402 (0402 (1005M) Capacitor)
pins: 1, 2

## GRM155R71E103JA01D
designator C?  Capacitance: 10nF  (hidden comment: *)
Capacitor, Ceramic (MLCC), 10nF, ±5%, ±5%, SMD 0402; Manufacturer: Murata Electronics; Manufacturer Part Number: GRM155R71E103JA01D
footprint CAP-0402 (0402 (1005M) Capacitor)
pins: 1, 2

## GRM155R71E103KA01D
designator C?  Capacitance: 10nF  (hidden comment: *)
Capacitor, Ceramic (MLCC), 10nF, ±10%, 25V, X7R, ±10%, SMD 0402; Manufacturer: Murata Electronics; Manufacturer Part Number: GRM155R71E103KA01D
footprint CAP-0402 (0402 (1005M) Capacitor)
pins: 1, 2

## GRM155R71E104KE14D
designator C?  Capacitance: 100nF  (hidden comment: *)
Capacitor, Ceramic (MLCC), 100nF, ±10%, 25V, X7R, ±10%, SMD 0402; Manufacturer: Murata Electronics; Manufacturer Part Number: GRM155R71E104KE14D
footprint CAP-0402 (0402 (1005M) Capacitor)
pins: 1, 2

## GRM155R71E153KA61D
designator C?  Capacitance: 15nF  (hidden comment: *)
Capacitor, Ceramic (MLCC), 15nF, ±10%, 25V, X7R, ±10%, SMD 0402; Manufacturer: Murata Electronics; Manufacturer Part Number: GRM155R71E153KA61D
footprint CAP-0402 (0402 (1005M) Capacitor)
pins: 1, 2

## GRM155R71E223JA61D
designator C?  Capacitance: 22nF  (hidden comment: *)
Capacitor, Ceramic (MLCC), 22nF, ±5%, 25V, X7R, ±5%, SMD 0402; Manufacturer: Murata Electronics; Manufacturer Part Number: GRM155R71E223JA61D
footprint CAP-0402 (0402 (1005M) Capacitor)
pins: 1, 2

## GRM155R71E393KA88D
designator C?  Capacitance: 39nF  (hidden comment: *)
Capacitor, Ceramic (MLCC), 39nF, ±10%, 25V, ±10%, SMD 0402; Manufacturer: Murata Electronics; Manufacturer Part Number: GRM155R71E393KA88D
footprint CAP-0402 (0402 (1005M) Capacitor)
pins: 1, 2

## GRM155R71E473JA88D
designator C?  Capacitance: 47nF  (hidden comment: *)
Capacitor, Ceramic (MLCC), 47nF, ±5%, 25V, X7R, ±5%, SMD 0402; Manufacturer: Murata Electronics; Manufacturer Part Number: GRM155R71E473JA88D
footprint CAP-0402 (0402 (1005M) Capacitor)
pins: 1, 2

## GRM155R71E822KA01D
designator C?  Capacitance: 8.2nF  (hidden comment: *)
Capacitor, Ceramic (MLCC), 8.2nF, ±10%, 25V, X7R, ±10%, SMD 0402; Manufacturer: Murata Electronics; Manufacturer Part Number: GRM155R71E822KA01D
footprint CAP-0402 (0402 (1005M) Capacitor)
pins: 1, 2

## GRM155R71H102JA01D
designator C?  Capacitance: 1nF  (hidden comment: *)
Capacitor, Ceramic (MLCC), 1nF, ±5%, 50V, X7R, ±5%, SMD 0402; Manufacturer: Murata Electronics; Manufacturer Part Number: GRM155R71H102JA01D
footprint CAP-0402 (0402 (1005M) Capacitor)
pins: 1, 2

## GRM155R71H102KA01D
designator C?  Capacitance: 1nF  (hidden comment: *)
Capacitor, Ceramic (MLCC), 1nF, ±10%, 50V, X7R, ±10%, SMD 0402; Manufacturer: Murata Electronics; Manufacturer Part Number: GRM155R71H102KA01D
footprint CAP-0402 (0402 (1005M) Capacitor)
pins: 1, 2

## GRM155R71H103JA88D
designator C?  Capacitance: 10nF  (hidden comment: *)
Capacitor, Ceramic (MLCC), 10nF, ±5%, 50V, ±5%, SMD 0402; Manufacturer: Murata Electronics; Manufacturer Part Number: GRM155R71H103JA88D
footprint CAP-0402 (0402 (1005M) Capacitor)
pins: 1, 2

## GRM155R71H103KA88D
designator C?  Capacitance: 10nF  (hidden comment: *)
Capacitor, Ceramic (MLCC), 10nF, ±10%, 50V, X7R, ±10%, SMD 0402; Manufacturer: Murata Electronics; Manufacturer Part Number: GRM155R71H103KA88D
footprint CAP-0402 (0402 (1005M) Capacitor)
pins: 1, 2

## GRM155R71H104KE14D
designator C?  Capacitance: 100nF  (hidden comment: *)
Capacitor, Ceramic (MLCC), 100nF, ±10%, 50V, X7R, ±10%, SMD 0402; Manufacturer: Murata Electronics; Manufacturer Part Number: GRM155R71H104KE14D
footprint CAP-0402 (0402 (1005M) Capacitor)
pins: 1, 2

## GRM155R71H122KA01D
designator C?  Capacitance: 1.2nF  (hidden comment: *)
Capacitor, Ceramic (MLCC), 1.2nF, ±10%, 50V, X7R, ±10%, SMD 0402; Manufacturer: Murata Electronics; Manufacturer Part Number: GRM155R71H122KA01D
footprint CAP-0402 (0402 (1005M) Capacitor)
pins: 1, 2

## GRM155R71H182JA01D
designator C?  Capacitance: 1.8nF  (hidden comment: *)
Capacitor, Ceramic (MLCC), 1.8nF, ±5%, 50V, X7R, ±5%, SMD 0402; Manufacturer: Murata Electronics; Manufacturer Part Number: GRM155R71H182JA01D
footprint CAP-0402 (0402 (1005M) Capacitor)
pins: 1, 2

## GRM155R71H182KA01D
designator C?  Capacitance: 1.8nF  (hidden comment: *)
Capacitor, Ceramic (MLCC), 1.8nF, ±10%, 50V, X7R, ±10%, SMD 0402; Manufacturer: Murata Electronics; Manufacturer Part Number: GRM155R71H182KA01D
footprint CAP-0402 (0402 (1005M) Capacitor)
pins: 1, 2

## GRM155R71H183KA12D
designator C?  Capacitance: 18nF  (hidden comment: *)
Capacitor, Ceramic (MLCC), 18nF, ±10%, 50V, X7R, ±10%, SMD 0402; Manufacturer: Murata Electronics; Manufacturer Part Number: GRM155R71H183KA12D
footprint CAP-0402 (0402 (1005M) Capacitor)
pins: 1, 2

## GRM155R71H222JA01D
designator C?  Capacitance: 2.2nF  (hidden comment: *)
Capacitor, Ceramic (MLCC), 2.2nF, ±5%, 50V, X7R, ±5%, SMD 0402; Manufacturer: Murata Electronics; Manufacturer Part Number: GRM155R71H222JA01D
footprint CAP-0402 (0402 (1005M) Capacitor)
pins: 1, 2

## GRM155R71H222KA01D
designator C?  Capacitance: 2.2nF  (hidden comment: *)
Capacitor, Ceramic (MLCC), 2.2nF, ±10%, 50V, X7R, ±10%, SMD 0402; Manufacturer: Murata Electronics; Manufacturer Part Number: GRM155R71H222KA01D
footprint CAP-0402 (0402 (1005M) Capacitor)
pins: 1, 2

## GRM155R71H223KA12D
designator C?  Capacitance: 22nF  (hidden comment: *)
Capacitor, Ceramic (MLCC), 22nF, ±10%, 50V, X7R, ±10%, SMD 0402; Manufacturer: Murata Electronics; Manufacturer Part Number: GRM155R71H223KA12D
footprint CAP-0402 (0402 (1005M) Capacitor)
pins: 1, 2

## GRM155R71H271KA01D
designator C?  Capacitance: 270pF  (hidden comment: *)
Capacitor, Ceramic (MLCC), 270pF, ±10%, 50V, X7R, ±10%, SMD 0402; Manufacturer: Murata Electronics; Manufacturer Part Number: GRM155R71H271KA01D
footprint CAP-0402 (0402 (1005M) Capacitor)
pins: 1, 2

## GRM155R71H332JA01D
designator C?  Capacitance: 3.3nF  (hidden comment: *)
Capacitor, Ceramic (MLCC), 3.3nF, ±5%, 50V, X7R, ±5%, SMD 0402; Manufacturer: Murata Electronics; Manufacturer Part Number: GRM155R71H332JA01D
footprint CAP-0402 (0402 (1005M) Capacitor)
pins: 1, 2

## GRM155R71H332KA01D
designator C?  Capacitance: 3.3nF  (hidden comment: *)
Capacitor, Ceramic (MLCC), 3.3nF, ±10%, 50V, X7R, ±10%, SMD 0402; Manufacturer: Murata Electronics; Manufacturer Part Number: GRM155R71H332KA01D
footprint CAP-0402 (0402 (1005M) Capacitor)
pins: 1, 2

## GRM155R71H333KE14D
designator C?  Capacitance: 33nF  (hidden comment: *)
Capacitor, Ceramic (MLCC), 33nF, ±10%, 50V, X7R, ±10%, SMD 0402; Manufacturer: Murata Electronics; Manufacturer Part Number: GRM155R71H333KE14D
footprint CAP-0402 (0402 (1005M) Capacitor)
pins: 1, 2

## GRM155R71H391KA01D
designator C?  Capacitance: 390pF  (hidden comment: *)
Capacitor, Ceramic (MLCC), 390pF, ±10%, 50V, X7R, ±10%, SMD 0402; Manufacturer: Murata Electronics; Manufacturer Part Number: GRM155R71H391KA01D
footprint CAP-0402 (0402 (1005M) Capacitor)
pins: 1, 2

## GRM155R71H471JA01D
designator C?  Capacitance: 470pF  (hidden comment: *)
Capacitor, Ceramic (MLCC), 470pF, ±5%, 50V, X7R, ±5%, SMD 0402; Manufacturer: Murata Electronics; Manufacturer Part Number: GRM155R71H471JA01D
footprint CAP-0402 (0402 (1005M) Capacitor)
pins: 1, 2

## GRM155R71H472JA01D
designator C?  Capacitance: 4.7nF  (hidden comment: *)
Capacitor, Ceramic (MLCC), 4.7nF, ±5%, ±5%, SMD 0402; Manufacturer: Murata Electronics; Manufacturer Part Number: GRM155R71H472JA01D
footprint CAP-0402 (0402 (1005M) Capacitor)
pins: 1, 2

## GRM155R71H472KA01D
designator C?  Capacitance: 4.7nF  (hidden comment: *)
Capacitor, Ceramic (MLCC), 4.7nF, ±10%, 50V, X7R, ±10%, SMD 0402; Manufacturer: Murata Electronics; Manufacturer Part Number: GRM155R71H472KA01D
footprint CAP-0402 (0402 (1005M) Capacitor)
pins: 1, 2

## GRM155R71H562KA88D
designator C?  Capacitance: 5.6nF  (hidden comment: *)
Capacitor, Ceramic (MLCC), 5.6nF, ±10%, 50V, X7R, ±10%, SMD 0402; Manufacturer: Murata Electronics; Manufacturer Part Number: GRM155R71H562KA88D
footprint CAP-0402 (0402 (1005M) Capacitor)
pins: 1, 2

## GRM155R72A221KA01D
designator C?  Capacitance: 220pF  (hidden comment: *)
Capacitor, Ceramic (MLCC), 220pF, ±10%, 100V, ±10%, SMD 0402; Manufacturer: Murata Electronics; Manufacturer Part Number: GRM155R72A221KA01D
footprint CAP-0402 (0402 (1005M) Capacitor)
pins: 1, 2

## GRM155R72A471KA01D
designator C?  Capacitance: 470pF  (hidden comment: *)
Capacitor, Ceramic (MLCC), 470pF, ±10%, 100V, X7R, ±10%, SMD 0402; Manufacturer: Murata Electronics; Manufacturer Part Number: GRM155R72A471KA01D
footprint CAP-0402 (0402 (1005M) Capacitor)
pins: 1, 2

## GRM155R72A472KA01D
designator C?  Capacitance: 4.7nF  (hidden comment: *)
Capacitor, Ceramic (MLCC), 4.7nF, ±10%, 100V, X7R, ±10%, SMD 0402; Manufacturer: Murata Electronics; Manufacturer Part Number: GRM155R72A472KA01D
footprint CAP-0402 (0402 (1005M) Capacitor)
pins: 1, 2

## GRM155R72A681KA01D
designator C?  Capacitance: 680pF  (hidden comment: *)
Capacitor, Ceramic (MLCC), 680pF, ±10%, 100V, X7R, ±10%, SMD 0402; Manufacturer: Murata Electronics; Manufacturer Part Number: GRM155R72A681KA01D
footprint CAP-0402 (0402 (1005M) Capacitor)
pins: 1, 2

## GRM155Z71A105KE01D
designator C?  Capacitance: 1uF  (hidden comment: *)
Capacitor, Ceramic (MLCC), 1uF, ±10%, 10V, X7R, ±10%, SMD 0402; Manufacturer: Murata Electronics; Manufacturer Part Number: GRM155Z71A105KE01D
footprint CAP-0402 (0402 (1005M) Capacitor)
pins: 1, 2

## GRM1552C1H102JA01D
designator C?  Capacitance: 1nF  (hidden comment: *)
Capacitor, Ceramic (MLCC), 1nF, ±5%, 50V, CH, ±5%, SMD 0402; Manufacturer: Murata Electronics; Manufacturer Part Number: GRM1552C1H102JA01D
footprint CAP-0402 (0402 (1005M) Capacitor)
pins: 1, 2

## GRM1552C1H150JA01D
designator C?  Capacitance: 15pF  (hidden comment: *)
Capacitor, Ceramic (MLCC), 15pF, ±5%, 50V, CH, ±5%, SMD 0402; Manufacturer: Murata Electronics; Manufacturer Part Number: GRM1552C1H150JA01D
footprint CAP-0402 (0402 (1005M) Capacitor)
pins: 1, 2

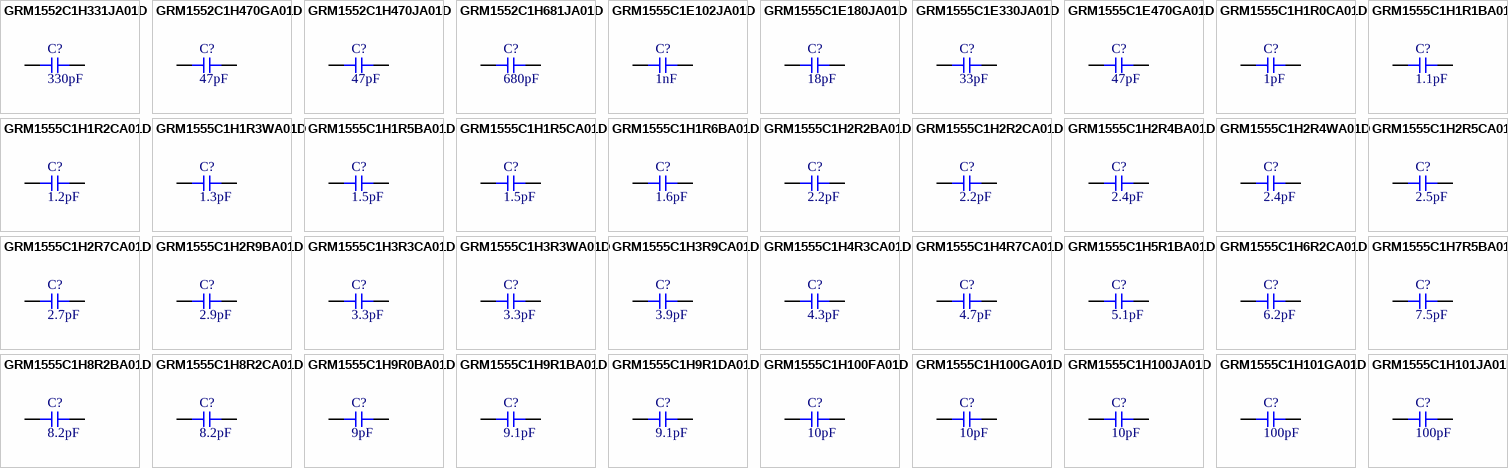
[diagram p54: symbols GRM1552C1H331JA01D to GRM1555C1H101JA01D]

## GRM1552C1H331JA01D
designator C?  Capacitance: 330pF  (hidden comment: *)
Capacitor, Ceramic (MLCC), 330pF, ±5%, 50V, CH, ±5%, SMD 0402; Manufacturer: Murata Electronics; Manufacturer Part Number: GRM1552C1H331JA01D
footprint CAP-0402 (0402 (1005M) Capacitor)
pins: 1, 2

## GRM1552C1H470GA01D
designator C?  Capacitance: 47pF  (hidden comment: *)
Capacitor, Ceramic (MLCC), 47pF, ±2%, ±2%, SMD 0402; Manufacturer: Murata Electronics; Manufacturer Part Number: GRM1552C1H470GA01D
footprint CAP-0402 (0402 (1005M) Capacitor)
pins: 1, 2

## GRM1552C1H470JA01D
designator C?  Capacitance: 47pF  (hidden comment: *)
Capacitor, Ceramic (MLCC), 47pF, ±5%, 50V, CH, ±5%, SMD 0402; Manufacturer: Murata Electronics; Manufacturer Part Number: GRM1552C1H470JA01D
footprint CAP-0402 (0402 (1005M) Capacitor)
pins: 1, 2

## GRM1552C1H681JA01D
designator C?  Capacitance: 680pF  (hidden comment: *)
Capacitor, Ceramic (MLCC), 680pF, ±5%, 50V, CH, ±5%, SMD 0402; Manufacturer: Murata Electronics; Manufacturer Part Number: GRM1552C1H681JA01D
footprint CAP-0402 (0402 (1005M) Capacitor)
pins: 1, 2

## GRM1555C1E102JA01D
designator C?  Capacitance: 1nF  (hidden comment: *)
Capacitor, Ceramic (MLCC), 1nF, ±5%, ±5%, SMD 0402; Manufacturer: Murata Electronics; Manufacturer Part Number: GRM1555C1E102JA01D
footprint CAP-0402 (0402 (1005M) Capacitor)
pins: 1, 2

## GRM1555C1E180JA01D
designator C?  Capacitance: 18pF  (hidden comment: *)
Capacitor, Ceramic (MLCC), 18pF, ±5%, 25V, C0G, ±5%, SMD 0402; Manufacturer: Murata Electronics; Manufacturer Part Number: GRM1555C1E180JA01D
footprint CAP-0402 (0402 (1005M) Capacitor)
pins: 1, 2

## GRM1555C1E330JA01D
designator C?  Capacitance: 33pF  (hidden comment: *)
Capacitor, Ceramic (MLCC), 33pF, ±5%, 25V, C0G, ±5%, SMD 0402; Manufacturer: Murata Electronics; Manufacturer Part Number: GRM1555C1E330JA01D
footprint CAP-0402 (0402 (1005M) Capacitor)
pins: 1, 2

## GRM1555C1E470GA01D
designator C?  Capacitance: 47pF  (hidden comment: *)
Capacitor, Ceramic (MLCC), 47pF, ±2%, 25V, C0G, ±2%, SMD 0402; Manufacturer: Murata Electronics; Manufacturer Part Number: GRM1555C1E470GA01D
footprint CAP-0402 (0402 (1005M) Capacitor)
pins: 1, 2

## GRM1555C1H1R0CA01D
designator C?  Capacitance: 1pF  (hidden comment: *)
Capacitor, Ceramic (MLCC), 1pF, ±0.25pF, 50V, C0G, ±0.25pF, SMD 0402; Manufacturer: Murata Electronics; Manufacturer Part Number: GRM1555C1H1R0CA01D
footprint CAP-0402 (0402 (1005M) Capacitor)
pins: 1, 2

## GRM1555C1H1R1BA01D
designator C?  Capacitance: 1.1pF  (hidden comment: *)
Capacitor, Ceramic (MLCC), 1.1pF, ±0.1pF, 50V, C0G, ±0.1pF, SMD 0402; Manufacturer: Murata Electronics; Manufacturer Part Number: GRM1555C1H1R1BA01D
footprint CAP-0402 (0402 (1005M) Capacitor)
pins: 1, 2

## GRM1555C1H1R2CA01D
designator C?  Capacitance: 1.2pF  (hidden comment: *)
Capacitor, Ceramic (MLCC), 1.2pF, ±0.25pF, 50V, C0G, ±0.25pF, SMD 0402; Manufacturer: Murata Electronics; Manufacturer Part Number: GRM1555C1H1R2CA01D
footprint CAP-0402 (0402 (1005M) Capacitor)
pins: 1, 2

## GRM1555C1H1R3WA01D
designator C?  Capacitance: 1.3pF  (hidden comment: *)
Capacitor, Ceramic (MLCC), 1.3pF, ±0.05pF, 50V, C0G, ±0.05pF, SMD 0402; Manufacturer: Murata Electronics; Manufacturer Part Number: GRM1555C1H1R3WA01D
footprint CAP-0402 (0402 (1005M) Capacitor)
pins: 1, 2

## GRM1555C1H1R5BA01D
designator C?  Capacitance: 1.5pF  (hidden comment: *)
Capacitor, Ceramic (MLCC), 1.5pF, ±0.1pF, 50V, C0G, ±0.1pF, SMD 0402; Manufacturer: Murata Electronics; Manufacturer Part Number: GRM1555C1H1R5BA01D
footprint CAP-0402 (0402 (1005M) Capacitor)
pins: 1, 2

## GRM1555C1H1R5CA01D
designator C?  Capacitance: 1.5pF  (hidden comment: *)
Capacitor, Ceramic (MLCC), 1.5pF, ±0.25pF, 50V, C0G, ±0.25pF, SMD 0402; Manufacturer: Murata Electronics; Manufacturer Part Number: GRM1555C1H1R5CA01D
footprint CAP-0402 (0402 (1005M) Capacitor)
pins: 1, 2

## GRM1555C1H1R6BA01D
designator C?  Capacitance: 1.6pF  (hidden comment: *)
Capacitor, Ceramic (MLCC), 1.6pF, ±0.1pF, 50V, C0G, ±0.1pF, SMD 0402; Manufacturer: Murata Electronics; Manufacturer Part Number: GRM1555C1H1R6BA01D
footprint CAP-0402 (0402 (1005M) Capacitor)
pins: 1, 2

## GRM1555C1H2R2BA01D
designator C?  Capacitance: 2.2pF  (hidden comment: *)
Capacitor, Ceramic (MLCC), 2.2pF, ±0.1pF, 50V, C0G, ±0.1pF, SMD 0402; Manufacturer: Murata Electronics; Manufacturer Part Number: GRM1555C1H2R2BA01D
footprint CAP-0402 (0402 (1005M) Capacitor)
pins: 1, 2

## GRM1555C1H2R2CA01D
designator C?  Capacitance: 2.2pF  (hidden comment: *)
Capacitor, Ceramic (MLCC), 2.2pF, ±0.25pF, 50V, C0G, ±0.25pF, SMD 0402; Manufacturer: Murata Electronics; Manufacturer Part Number: GRM1555C1H2R2CA01D
footprint CAP-0402 (0402 (1005M) Capacitor)
pins: 1, 2

## GRM1555C1H2R4BA01D
designator C?  Capacitance: 2.4pF  (hidden comment: *)
Capacitor, Ceramic (MLCC), 2.4pF, ±0.1pF, 50V, C0G, ±0.1pF, SMD 0402; Manufacturer: Murata Electronics; Manufacturer Part Number: GRM1555C1H2R4BA01D
footprint CAP-0402 (0402 (1005M) Capacitor)
pins: 1, 2

## GRM1555C1H2R4WA01D
designator C?  Capacitance: 2.4pF  (hidden comment: *)
Capacitor, Ceramic (MLCC), 2.4pF, SMD 0402; Manufacturer: Murata Electronics; Manufacturer Part Number: GRM1555C1H2R4WA01D
footprint CAP-0402 (0402 (1005M) Capacitor)
pins: 1, 2

## GRM1555C1H2R5CA01D
designator C?  Capacitance: 2.5pF  (hidden comment: *)
Capacitor, Ceramic (MLCC), 2.5pF, ±0.25pF, 50V, C0G, ±0.25pF, SMD 0402; Manufacturer: Murata Electronics; Manufacturer Part Number: GRM1555C1H2R5CA01D
footprint CAP-0402 (0402 (1005M) Capacitor)
pins: 1, 2

## GRM1555C1H2R7CA01D
designator C?  Capacitance: 2.7pF  (hidden comment: *)
Capacitor, Ceramic (MLCC), 2.7pF, ±0.25pF, 50V, C0G, ±0.25pF, SMD 0402; Manufacturer: Murata Electronics; Manufacturer Part Number: GRM1555C1H2R7CA01D
footprint CAP-0402 (0402 (1005M) Capacitor)
pins: 1, 2

## GRM1555C1H2R9BA01D
designator C?  Capacitance: 2.9pF  (hidden comment: *)
Capacitor, Ceramic (MLCC), 2.9pF, ±0.1pF, 50V, C0G, ±0.1pF, SMD 0402; Manufacturer: Murata Electronics; Manufacturer Part Number: GRM1555C1H2R9BA01D
footprint CAP-0402 (0402 (1005M) Capacitor)
pins: 1, 2

## GRM1555C1H3R3CA01D
designator C?  Capacitance: 3.3pF  (hidden comment: *)
Capacitor, Ceramic (MLCC), 3.3pF, ±0.25pF, 50V, C0G, ±0.25pF, SMD 0402; Manufacturer: Murata Electronics; Manufacturer Part Number: GRM1555C1H3R3CA01D
footprint CAP-0402 (0402 (1005M) Capacitor)
pins: 1, 2

## GRM1555C1H3R3WA01D
designator C?  Capacitance: 3.3pF  (hidden comment: *)
Capacitor, Ceramic (MLCC), 3.3pF, ±0.05pF, 50V, C0G, ±0.05pF, SMD 0402; Manufacturer: Murata Electronics; Manufacturer Part Number: GRM1555C1H3R3WA01D
footprint CAP-0402 (0402 (1005M) Capacitor)
pins: 1, 2

## GRM1555C1H3R9CA01D
designator C?  Capacitance: 3.9pF  (hidden comment: *)
Capacitor, Ceramic (MLCC), 3.9pF, ±0.25pF, 50V, C0G, ±0.25pF, SMD 0402; Manufacturer: Murata Electronics; Manufacturer Part Number: GRM1555C1H3R9CA01D
footprint CAP-0402 (0402 (1005M) Capacitor)
pins: 1, 2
